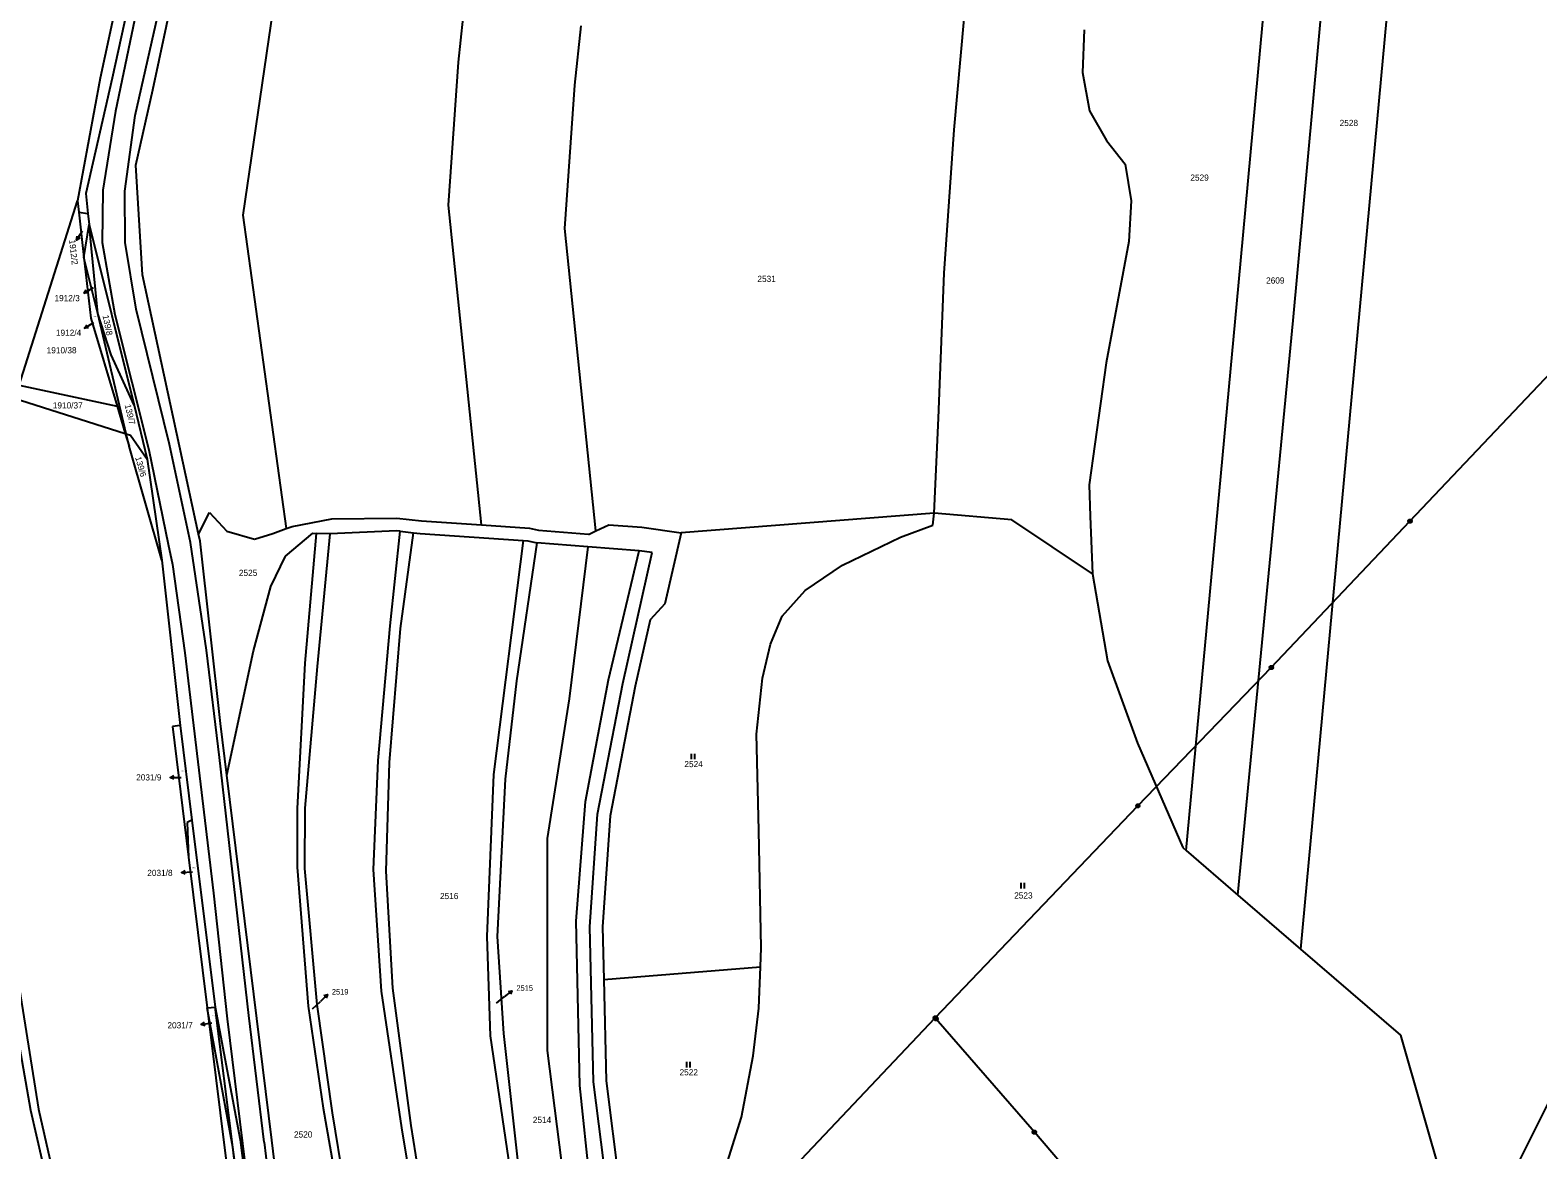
# Model space of a CAD drawing. Extents: x -609861 to -605046, y -1120287 to -1116307.
# Drawn here: x -607250.8 to -606836.4, y -1118504.6 to -1118197.1 of the extents above; entities that cross this region are included whole.
import ezdxf

# ---------------------------------------------------------------- set-up
doc = ezdxf.new("R2010")
doc.units = 0
for name, color, linetype in [('Vrstva 1', 7, 'Continuous'), ('Vrstva 2', 7, 'Continuous'), ('Vrstva 3', 7, 'Continuous'), ('Vrstva 4', 7, 'Continuous'), ('Vrstva 6', 7, 'Continuous'), ('Vrstva 7', 7, 'Continuous')]:
    doc.layers.add(name, color=color, linetype=linetype)

msp = doc.modelspace()

# ---------------------------------------------------------------- linework, layer by layer
at = {"layer": 'Vrstva 1'}
for p, q in [((-607172.46, -1118111.92), (-607192.3, -1118247.91)), ((-606918.73, -1118267.31), (-606904.4, -1118112.2)), ((-606903.66, -1118276.82), (-606888.63, -1118111.38)), ((-606870.35, -1118110.42), (-606886.02, -1118279.96)), ((-607212.94, -1118123.59), (-607231.55, -1118210.23)), ((-607209.11, -1118122.88), (-607228.2, -1118210.25)), ((-607217.05, -1118213.46), (-607198.16, -1118124.63)), ((-607133.04, -1118205.81), (-607126.84, -1118146.88)), ((-606996.8, -1118224.45), (-606994.05, -1118193.91)), ((-607101.05, -1118212.2), (-607099.33, -1118195.85)), ((-606961.13, -1118196.96), (-606961.53, -1118208.68)), ((-607135.82, -1118245.13), (-607133.04, -1118205.81)), ((-607231.55, -1118210.23), (-607237.75, -1118243.93)), ((-607228.2, -1118210.25), (-607235.42, -1118241.92)), ((-607103.83, -1118251.52), (-607101.05, -1118212.2)), ((-606961.53, -1118208.68), (-606959.68, -1118219.21)), ((-607221.72, -1118234.16), (-607217.05, -1118213.46)), ((-606959.68, -1118219.21), (-606954.98, -1118227.39)), ((-606999.58, -1118263.77), (-606996.8, -1118224.45)), ((-606954.98, -1118227.39), (-606949.83, -1118233.88)), ((-607219.92, -1118264.25), (-607221.72, -1118234.16)), ((-606949.83, -1118233.88), (-606948.16, -1118243.99)), ((-607253.78, -1118294.59), (-607237.75, -1118243.93)), ((-607237.75, -1118243.93), (-607237.39, -1118247.08)), ((-607235.42, -1118241.92), (-607234.88, -1118247.44)), ((-607126.76, -1118332.97), (-607135.82, -1118245.13)), ((-606948.16, -1118243.99), (-606948.82, -1118255.1)), ((-607237.39, -1118247.08), (-607234.88, -1118247.44)), ((-607237.39, -1118247.08), (-607235.98, -1118259.51)), ((-607234.88, -1118247.44), (-607234.58, -1118250.49)), ((-607192.3, -1118247.91), (-607180.37, -1118333.98)), ((-607235.98, -1118259.51), (-607234.58, -1118250.49)), ((-607232.18, -1118274.91), (-607234.58, -1118250.49)), ((-607234.58, -1118250.49), (-607222.16, -1118300.08)), ((-607095.27, -1118334.57), (-607103.83, -1118251.52)), ((-606948.82, -1118255.1), (-606955.03, -1118288.41)), ((-607232.18, -1118274.91), (-607235.98, -1118259.51)), ((-607235.98, -1118259.51), (-607234.08, -1118276.2)), ((-607204.46, -1118335.48), (-607219.92, -1118264.25)), ((-607001.11, -1118303.67), (-606999.58, -1118263.77)), ((-606933.06, -1118422.42), (-606918.73, -1118267.31)), ((-607234.08, -1118276.2), (-607226.84, -1118300.38)), ((-607228.45, -1118286.25), (-607232.18, -1118274.91)), ((-607224.37, -1118307.94), (-607232.18, -1118274.91)), ((-606918.9, -1118434.64), (-606903.66, -1118276.82)), ((-606886.02, -1118279.96), (-606901.68, -1118449.49)), ((-607222.16, -1118300.08), (-607228.45, -1118286.25)), ((-606955.03, -1118288.41), (-606959.74, -1118322)), ((-607253.78, -1118294.59), (-607226.84, -1118300.38)), ((-607255.46, -1118298.06), (-607224.61, -1118307.86)), ((-607226.84, -1118300.38), (-607224.61, -1118307.86)), ((-607222.16, -1118300.08), (-607218.61, -1118314.91)), ((-607002.36, -1118329.74), (-607001.11, -1118303.67)), ((-607224.61, -1118307.86), (-607223.56, -1118311.36)), ((-607224.37, -1118307.94), (-607223.19, -1118308.31)), ((-607223.56, -1118311.36), (-607224.37, -1118307.94)), ((-607214.6, -1118342.67), (-607223.56, -1118311.36)), ((-607223.19, -1118308.31), (-607218.61, -1118314.91)), ((-607218.61, -1118314.91), (-607214.6, -1118342.67)), ((-606959.74, -1118322), (-606959.43, -1118330.56)), ((-607204.46, -1118335.48), (-607201.5, -1118329.59)), ((-607201.5, -1118329.59), (-607196.7, -1118334.64)), ((-607178.71, -1118333.37), (-607167.89, -1118331.31)), ((-607167.89, -1118331.31), (-607149.98, -1118331.07)), ((-607149.98, -1118331.07), (-607143.25, -1118331.83)), ((-607143.25, -1118331.83), (-607126.76, -1118332.97)), ((-607002.36, -1118329.74), (-607071.9, -1118335.13)), ((-607002.66, -1118333.04), (-607002.36, -1118329.74)), ((-606980.96, -1118331.55), (-607002.36, -1118329.74)), ((-606958.86, -1118346.42), (-606980.96, -1118331.55)), ((-606959.43, -1118330.56), (-606958.86, -1118346.42)), ((-607204.04, -1118337.4), (-607204.46, -1118335.48)), ((-607196.7, -1118334.64), (-607189.07, -1118336.84)), ((-607189.07, -1118336.84), (-607184.05, -1118335.32)), ((-607184.05, -1118335.32), (-607180.37, -1118333.98)), ((-607180.56, -1118341.58), (-607173.06, -1118335.25)), ((-607180.37, -1118333.98), (-607178.71, -1118333.37)), ((-607172.16, -1118335.31), (-607175.25, -1118370.95)), ((-607173.06, -1118335.25), (-607172.16, -1118335.31)), ((-607168.35, -1118335.42), (-607172.16, -1118335.31)), ((-607171.79, -1118371.87), (-607168.35, -1118335.42)), ((-607150.1, -1118334.58), (-607168.35, -1118335.42)), ((-607151.84, -1118360.64), (-607149.12, -1118334.65)), ((-607149.12, -1118334.65), (-607150.1, -1118334.58)), ((-607149.12, -1118334.65), (-607145.38, -1118335.12)), ((-607149, -1118361.46), (-607145.38, -1118335.12)), ((-607145.38, -1118335.12), (-607143.57, -1118335.32)), ((-607143.57, -1118335.32), (-607115.24, -1118337.28)), ((-607126.76, -1118332.97), (-607113.57, -1118333.89)), ((-607113.57, -1118333.89), (-607111.05, -1118334.41)), ((-607111.05, -1118334.41), (-607097.3, -1118335.48)), ((-607097.3, -1118335.48), (-607097.18, -1118335.49)), ((-607097.18, -1118335.49), (-607095.27, -1118334.57)), ((-607095.27, -1118334.57), (-607091.77, -1118332.9)), ((-607091.77, -1118332.9), (-607082.69, -1118333.61)), ((-607082.69, -1118333.61), (-607071.9, -1118335.13)), ((-607071.9, -1118335.13), (-607076.3, -1118354.64)), ((-607027.54, -1118344), (-607011.59, -1118336.34)), ((-607011.59, -1118336.34), (-607002.66, -1118333.04)), ((-607198.43, -1118387.5), (-607204.04, -1118337.4)), ((-607115.24, -1118337.28), (-607123.4, -1118401.56)), ((-607111.54, -1118337.88), (-607117.09, -1118375.75)), ((-607115.24, -1118337.28), (-607114.03, -1118337.35)), ((-607114.03, -1118337.35), (-607111.54, -1118337.88)), ((-607097.47, -1118338.98), (-607111.54, -1118337.88)), ((-607097.47, -1118338.98), (-607102.63, -1118380.78)), ((-607083.4, -1118340.07), (-607097.47, -1118338.98)), ((-607091.8, -1118375.49), (-607083.4, -1118340.07)), ((-607087.92, -1118376.55), (-607079.79, -1118340.58)), ((-607079.79, -1118340.58), (-607083.4, -1118340.07)), ((-607214.6, -1118342.67), (-607209.57, -1118388.09)), ((-607184.64, -1118349.84), (-607180.56, -1118341.58)), ((-607037.75, -1118351.02), (-607027.54, -1118344)), ((-606958.86, -1118346.42), (-606954.68, -1118370.27)), ((-607189.42, -1118367.52), (-607184.64, -1118349.84)), ((-607044.13, -1118358.05), (-607037.75, -1118351.02)), ((-607076.3, -1118354.64), (-607080.38, -1118359.05)), ((-607155.09, -1118397.64), (-607151.84, -1118360.64)), ((-607152.01, -1118398.25), (-607149, -1118361.46)), ((-607080.38, -1118359.05), (-607084.49, -1118377.27)), ((-607047.32, -1118365.71), (-607044.13, -1118358.05)), ((-607196.68, -1118401.73), (-607189.42, -1118367.52)), ((-607049.55, -1118375.09), (-607047.32, -1118365.71)), ((-607175.25, -1118370.95), (-607177.42, -1118410.88)), ((-607175.14, -1118410.78), (-607171.79, -1118371.87)), ((-606954.68, -1118370.27), (-606946.43, -1118392.95)), ((-607117.09, -1118375.75), (-607120.18, -1118402.77)), ((-607098.14, -1118408.97), (-607091.8, -1118375.49)), ((-607094.87, -1118412.42), (-607087.92, -1118376.55)), ((-607084.49, -1118377.27), (-607091.39, -1118412.87)), ((-607051.14, -1118390.42), (-607049.55, -1118375.09)), ((-607102.63, -1118380.78), (-607108.64, -1118419.12)), ((-607209.57, -1118388.09), (-607211.63, -1118388.37)), ((-607211.63, -1118388.37), (-607207.21, -1118424.22)), ((-607209.57, -1118388.09), (-607206.32, -1118414.02)), ((-607196.68, -1118401.73), (-607198.43, -1118387.5)), ((-607050.5, -1118416.91), (-607051.14, -1118390.42)), ((-606946.43, -1118392.95), (-606934.03, -1118421.58)), ((-607156.38, -1118427.64), (-607155.09, -1118397.64)), ((-607152.96, -1118428.06), (-607152.01, -1118398.25)), ((-607184.37, -1118502.01), (-607196.68, -1118401.73)), ((-607123.4, -1118401.56), (-607125.22, -1118446)), ((-607120.18, -1118402.77), (-607122.42, -1118446)), ((-607177.42, -1118410.88), (-607177.42, -1118426.96)), ((-607175.23, -1118427.37), (-607175.14, -1118410.78)), ((-607100.67, -1118441.85), (-607098.14, -1118408.97)), ((-607206.32, -1118414.02), (-607207.57, -1118414.74)), ((-607207.57, -1118414.74), (-607207.21, -1118424.22)), ((-607206.32, -1118414.02), (-607199.88, -1118465.43)), ((-607096.96, -1118443.33), (-607094.87, -1118412.42)), ((-607091.39, -1118412.87), (-607093.46, -1118443.41)), ((-607108.64, -1118419.12), (-607108.64, -1118477.33)), ((-607049.86, -1118449.16), (-607050.5, -1118416.91)), ((-606934.03, -1118421.58), (-606933.06, -1118422.42)), ((-606933.06, -1118422.42), (-606918.9, -1118434.64)), ((-607207.21, -1118424.22), (-607202.11, -1118465.65)), ((-607177.42, -1118426.96), (-607174.35, -1118465.12)), ((-607171.93, -1118464.66), (-607175.23, -1118427.37)), ((-607154.21, -1118461), (-607156.38, -1118427.64)), ((-607151.1, -1118460.25), (-607152.96, -1118428.06)), ((-606918.9, -1118434.64), (-606901.68, -1118449.49)), ((-606805.82, -1118435.99), (-606851.98, -1118528.42)), ((-607099.72, -1118486.99), (-607100.67, -1118441.85)), ((-607095.91, -1118485.91), (-607096.96, -1118443.33)), ((-607093.46, -1118443.41), (-607093.1, -1118457.87)), ((-607125.22, -1118446), (-607124.32, -1118473.3)), ((-607122.42, -1118446), (-607120.64, -1118472.66)), ((-607050.06, -1118454.33), (-607049.86, -1118449.16)), ((-606901.68, -1118449.49), (-606874.22, -1118473.16)), ((-607254.29, -1118456.53), (-607248.49, -1118493.49)), ((-607093.1, -1118457.87), (-607050.06, -1118454.33)), ((-607050.5, -1118465.67), (-607050.06, -1118454.33)), ((-607257.06, -1118456.98), (-607250.62, -1118493.73)), ((-607146.07, -1118497.94), (-607151.1, -1118460.25)), ((-607093.1, -1118457.87), (-607092.42, -1118485.65)), ((-607167.71, -1118494.46), (-607171.93, -1118464.66)), ((-607148.58, -1118498.62), (-607154.21, -1118461)), ((-607202.11, -1118465.65), (-607199.88, -1118465.43)), ((-607195.06, -1118503.92), (-607202.11, -1118465.65)), ((-607202.11, -1118465.65), (-607197.37, -1118504.09)), ((-607195.06, -1118503.92), (-607199.88, -1118465.43)), ((-607199.88, -1118465.43), (-607193.08, -1118501.84)), ((-607174.35, -1118465.12), (-607170.21, -1118493.2)), ((-607052.09, -1118478.76), (-607050.5, -1118465.67)), ((-607124.32, -1118473.3), (-607118.94, -1118509.95)), ((-607120.64, -1118472.66), (-607116.66, -1118509.04)), ((-606874.22, -1118473.16), (-606857.36, -1118531.64)), ((-607108.64, -1118477.33), (-607103.27, -1118519.64)), ((-607055.28, -1118495.68), (-607052.09, -1118478.76)), ((-607092.42, -1118485.65), (-607088.74, -1118515.16)), ((-607095.7, -1118525.1), (-607099.72, -1118486.99)), ((-607091.13, -1118524.28), (-607095.91, -1118485.91)), ((-607250.62, -1118493.73), (-607238.38, -1118547.37)), ((-607248.49, -1118493.49), (-607236.26, -1118546.93)), ((-607170.21, -1118493.2), (-607162.96, -1118534.58)), ((-607161.12, -1118534.04), (-607167.71, -1118494.46)), ((-607139.78, -1118536.75), (-607146.07, -1118497.94)), ((-607062.62, -1118518.98), (-607055.28, -1118495.68)), ((-607193.08, -1118501.84), (-607179.6, -1118606.23)), ((-607171.11, -1118605.54), (-607184.37, -1118502.01)), ((-607142.16, -1118537.19), (-607148.58, -1118498.62)), ((-607197.37, -1118504.09), (-607189.06, -1118569.6)), ((-607182.6, -1118596.66), (-607195.06, -1118503.92)), ((-607187.79, -1118564.73), (-607195.06, -1118503.92))]:
    msp.add_line(p, q, dxfattribs=at)
at = {"layer": 'Vrstva 3'}
for p, q in [((-607069.11, -1118395.8), (-607069.11, -1118397.3)), ((-607068.11, -1118397.3), (-607068.11, -1118395.8)), ((-606978.48, -1118431.3), (-606978.48, -1118432.8)), ((-606977.48, -1118432.8), (-606977.48, -1118431.3)), ((-607070.37, -1118480.47), (-607070.37, -1118481.97)), ((-607069.37, -1118481.97), (-607069.37, -1118480.47))]:
    msp.add_line(p, q, dxfattribs=at)
at = {"layer": 'Vrstva 4'}
for p, q in [((-607219.45, -1118181.73), (-607227.28, -1118219.31)), ((-607221.87, -1118220.52), (-607213.45, -1118182.9)), ((-607227.28, -1118219.31), (-607230.78, -1118241.02)), ((-607224.78, -1118241.29), (-607221.87, -1118220.52)), ((-607230.78, -1118241.02), (-607230.98, -1118255.4)), ((-607224.68, -1118255.38), (-607224.78, -1118241.29)), ((-607230.98, -1118255.4), (-607227.5, -1118275.18)), ((-607221.66, -1118273.69), (-607224.68, -1118255.38)), ((-607212.45, -1118310.87), (-607221.66, -1118273.69)), ((-607227.5, -1118275.18), (-607218.14, -1118312.3)), ((-607206.72, -1118337.75), (-607212.45, -1118310.87)), ((-607218.14, -1118312.3), (-607212.82, -1118338.27)), ((-607212.82, -1118338.27), (-607211.6, -1118343.82)), ((-607202.28, -1118367.34), (-607206.72, -1118337.75)), ((-607211.6, -1118343.82), (-607208.22, -1118368.1)), ((-607208.22, -1118368.1), (-607200.4, -1118434.15)), ((-607198.72, -1118396.82), (-607202.28, -1118367.34)), ((-607190.64, -1118467.75), (-607198.72, -1118396.82)), ((-607200.4, -1118434.15), (-607196.66, -1118468.6)), ((-607196.66, -1118468.6), (-607188.25, -1118535.94)), ((-607186.47, -1118502.52), (-607190.64, -1118467.75)), ((-607186.47, -1118502.52), (-607174.59, -1118597.34))]:
    msp.add_line(p, q, dxfattribs=at)
at = {"layer": 'Vrstva 6'}
for p, q in [((-606871.61, -1118331.95), (-606829.45, -1118287.55)), ((-606909.71, -1118372.14), (-606871.61, -1118331.95)), ((-606946.37, -1118410.11), (-606909.71, -1118372.14)), ((-607002.05, -1118468.39), (-606946.37, -1118410.11)), ((-607046.72, -1118515.53), (-607002.05, -1118468.39)), ((-606974.78, -1118499.79), (-607001.86, -1118468.65)), ((-606930.18, -1118551.66), (-606974.78, -1118499.79))]:
    msp.add_line(p, q, dxfattribs=at)
for points in [[(-606871.76, -1118331.47), (-606871.45, -1118331.47), (-606871.2, -1118331.65), (-606871.1, -1118331.94), (-606871.2, -1118332.23), (-606871.45, -1118332.41), (-606871.76, -1118332.41), (-606872.01, -1118332.23), (-606872.11, -1118331.94), (-606872.01, -1118331.65), (-606871.76, -1118331.47), (-606871.73, -1118331.51), (-606871.49, -1118331.51), (-606871.33, -1118331.59), (-606871.89, -1118331.59), (-606871.97, -1118331.67), (-606871.25, -1118331.67), (-606871.25, -1118331.75), (-606871.97, -1118331.75), (-606872.01, -1118331.83), (-606871.21, -1118331.83), (-606871.17, -1118331.91), (-606872.05, -1118331.91), (-606872.05, -1118331.99), (-606871.17, -1118331.99), (-606871.2, -1118332.07), (-606872.01, -1118332.07), (-606872, -1118332.15), (-606871.19, -1118332.15), (-606871.24, -1118332.23), (-606871.96, -1118332.23), (-606871.88, -1118332.31), (-606871.32, -1118332.31), (-606871.43, -1118332.39), (-606871.77, -1118332.39)], [(-606909.86, -1118371.66), (-606909.55, -1118371.66), (-606909.3, -1118371.84), (-606909.2, -1118372.13), (-606909.3, -1118372.42), (-606909.55, -1118372.6), (-606909.86, -1118372.6), (-606910.11, -1118372.42), (-606910.21, -1118372.13), (-606910.11, -1118371.84), (-606909.86, -1118371.66), (-606909.83, -1118371.7), (-606909.59, -1118371.7), (-606909.43, -1118371.78), (-606909.99, -1118371.78), (-606910.07, -1118371.86), (-606909.35, -1118371.86), (-606909.35, -1118371.94), (-606910.07, -1118371.94), (-606910.11, -1118372.02), (-606909.31, -1118372.02), (-606909.27, -1118372.1), (-606910.15, -1118372.1), (-606910.15, -1118372.18), (-606909.27, -1118372.18), (-606909.3, -1118372.26), (-606910.11, -1118372.26), (-606910.1, -1118372.34), (-606909.29, -1118372.34), (-606909.34, -1118372.42), (-606910.06, -1118372.42), (-606909.98, -1118372.5), (-606909.42, -1118372.5), (-606909.53, -1118372.58), (-606909.87, -1118372.58)], [(-606946.52, -1118409.63), (-606946.21, -1118409.63), (-606945.96, -1118409.81), (-606945.86, -1118410.1), (-606945.96, -1118410.39), (-606946.21, -1118410.57), (-606946.52, -1118410.57), (-606946.77, -1118410.39), (-606946.87, -1118410.1), (-606946.77, -1118409.81), (-606946.52, -1118409.63), (-606946.49, -1118409.67), (-606946.25, -1118409.67), (-606946.09, -1118409.75), (-606946.65, -1118409.75), (-606946.73, -1118409.83), (-606946.01, -1118409.83), (-606946.01, -1118409.91), (-606946.73, -1118409.91), (-606946.77, -1118409.99), (-606945.97, -1118409.99), (-606945.93, -1118410.07), (-606946.81, -1118410.07), (-606946.81, -1118410.15), (-606945.93, -1118410.15), (-606945.96, -1118410.23), (-606946.77, -1118410.23), (-606946.76, -1118410.31), (-606945.95, -1118410.31), (-606946, -1118410.39), (-606946.72, -1118410.39), (-606946.64, -1118410.47), (-606946.08, -1118410.47), (-606946.19, -1118410.55), (-606946.53, -1118410.55)], [(-607002.2, -1118467.91), (-607001.89, -1118467.91), (-607001.64, -1118468.09), (-607001.54, -1118468.38), (-607001.64, -1118468.67), (-607001.89, -1118468.85), (-607002.2, -1118468.85), (-607002.45, -1118468.67), (-607002.55, -1118468.38), (-607002.45, -1118468.09), (-607002.2, -1118467.91), (-607002.17, -1118467.95), (-607001.93, -1118467.95), (-607001.77, -1118468.03), (-607002.33, -1118468.03), (-607002.41, -1118468.11), (-607001.69, -1118468.11), (-607001.69, -1118468.19), (-607002.41, -1118468.19), (-607002.45, -1118468.27), (-607001.65, -1118468.27), (-607001.61, -1118468.35), (-607002.49, -1118468.35), (-607002.49, -1118468.43), (-607001.61, -1118468.43), (-607001.64, -1118468.51), (-607002.45, -1118468.51), (-607002.44, -1118468.59), (-607001.63, -1118468.59), (-607001.68, -1118468.67), (-607002.4, -1118468.67), (-607002.32, -1118468.75), (-607001.76, -1118468.75), (-607001.87, -1118468.83), (-607002.21, -1118468.83)], [(-607002.01, -1118468.17), (-607001.7, -1118468.17), (-607001.45, -1118468.35), (-607001.35, -1118468.64), (-607001.45, -1118468.93), (-607001.7, -1118469.11), (-607002.01, -1118469.11), (-607002.26, -1118468.93), (-607002.36, -1118468.64), (-607002.26, -1118468.35), (-607002.01, -1118468.17), (-607001.98, -1118468.21), (-607001.74, -1118468.21), (-607001.58, -1118468.29), (-607002.14, -1118468.29), (-607002.22, -1118468.37), (-607001.5, -1118468.37), (-607001.5, -1118468.45), (-607002.22, -1118468.45), (-607002.26, -1118468.53), (-607001.46, -1118468.53), (-607001.42, -1118468.61), (-607002.3, -1118468.61), (-607002.3, -1118468.69), (-607001.42, -1118468.69), (-607001.45, -1118468.77), (-607002.26, -1118468.77), (-607002.25, -1118468.85), (-607001.44, -1118468.85), (-607001.49, -1118468.93), (-607002.21, -1118468.93), (-607002.13, -1118469.01), (-607001.57, -1118469.01), (-607001.68, -1118469.09), (-607002.02, -1118469.09)], [(-606974.93, -1118499.31), (-606974.62, -1118499.31), (-606974.37, -1118499.49), (-606974.27, -1118499.78), (-606974.37, -1118500.07), (-606974.62, -1118500.25), (-606974.93, -1118500.25), (-606975.18, -1118500.07), (-606975.28, -1118499.78), (-606975.18, -1118499.49), (-606974.93, -1118499.31), (-606974.9, -1118499.35), (-606974.66, -1118499.35), (-606974.5, -1118499.43), (-606975.06, -1118499.43), (-606975.14, -1118499.51), (-606974.42, -1118499.51), (-606974.42, -1118499.59), (-606975.14, -1118499.59), (-606975.18, -1118499.67), (-606974.38, -1118499.67), (-606974.34, -1118499.75), (-606975.22, -1118499.75), (-606975.22, -1118499.83), (-606974.34, -1118499.83), (-606974.37, -1118499.91), (-606975.18, -1118499.91), (-606975.17, -1118499.99), (-606974.36, -1118499.99), (-606974.41, -1118500.07), (-606975.13, -1118500.07), (-606975.05, -1118500.15), (-606974.49, -1118500.15), (-606974.6, -1118500.23), (-606974.94, -1118500.23)]]:
    msp.add_lwpolyline(points, dxfattribs=at)
at = {"layer": 'Vrstva 7'}
for p, q in [((-607238.003, -1118254.733), (-607236.35, -1118252.23)), ((-607235.921, -1118269.326), (-607233.35, -1118267.78)), ((-607235.817, -1118278.943), (-607233.25, -1118277.39)), ((-607212.25, -1118402.311), (-607209.25, -1118402.31)), ((-607209.161, -1118428.471), (-607206.17, -1118428.24)), ((-607173.15, -1118465.91), (-607171, -1118463.84)), ((-607169.057, -1118461.965), (-607171, -1118463.84)), ((-607122.58, -1118464.31), (-607120.46, -1118462.62)), ((-607118.345, -1118460.942), (-607120.46, -1118462.62)), ((-607203.757, -1118470.238), (-607200.8, -1118469.73))]:
    msp.add_line(p, q, dxfattribs=at)
for points in [[(-607237.035, -1118254.174), (-607238.003, -1118254.733), (-607237.869, -1118253.623)], [(-607234.807, -1118269.239), (-607235.921, -1118269.326), (-607235.322, -1118268.382)], [(-607234.702, -1118278.853), (-607235.817, -1118278.943), (-607235.22, -1118277.998)], [(-607211.25, -1118402.81), (-607212.25, -1118402.311), (-607211.25, -1118401.81)], [(-607208.125, -1118428.893), (-607209.161, -1118428.471), (-607208.203, -1118427.896)], [(-607170.017, -1118462.266), (-607169.057, -1118461.965), (-607169.392, -1118462.914)], [(-607119.329, -1118461.149), (-607118.345, -1118460.942), (-607118.77, -1118461.854)], [(-607202.686, -1118470.562), (-607203.757, -1118470.238), (-607202.856, -1118469.576)]]:
    msp.add_lwpolyline(points, dxfattribs=at)

# ---------------------------------------------------------------- texts
at = {"layer": 'Vrstva 2'}
for s, height, p in [('2528', 1.7, (-606890.903, -1118223.4)), ('2529', 1.7, (-606931.923, -1118238.42)), ('1912/2', 0.2, (-607235.864, -1118250.5)), ('1912/3', 0.2, (-607234.604, -1118260.6)), ('2531', 1.7, (-607050.903, -1118266.23)), ('2609', 1.7, (-606911.113, -1118266.67)), ('1912/4', 0.2, (-607233.304, -1118275.81)), ('1910/38', 1.7, (-607246.217, -1118285.84)), ('1910/37', 1.7, (-607244.537, -1118300.98)), ('2525', 1.7, (-607193.393, -1118346.98)), ('2524', 1.7, (-607070.973, -1118399.5)), ('2031/9', 0.2, (-607209.222, -1118400.7)), ('2031/8', 0.2, (-607206.142, -1118427.26)), ('2516', 1.7, (-607138.133, -1118435.75)), ('2523', 1.7, (-606980.333, -1118435.59)), ('2515', 0.1, (-607122.566, -1118464.31)), ('2031/7', 0.2, (-607200.772, -1118467.98)), ('2519', 0.1, (-607173.136, -1118465.91)), ('2522', 1.7, (-607072.303, -1118484.17)), ('2514', 1.7, (-607112.623, -1118497.23)), ('2520', 1.7, (-607178.253, -1118501.24))]:
    msp.add_text(s, height=height, dxfattribs=at).set_placement(p)
for s, rotation, p in [('139/8', 281.72335, (-607230.87, -1118275.495)), ('139/7', 283.49952, (-607224.788, -1118300.052)), ('139/6', 285.27569, (-607221.917, -1118314.429))]:
    msp.add_text(s, height=1.7, rotation=rotation, dxfattribs=at).set_placement(p)
at = {"layer": 'Vrstva 7'}
msp.add_text('1912/2', height=1.7, rotation=276.28025, dxfattribs=at).set_placement((-607240.048, -1118254.685))
for s, height, p in [('1912/3', 1.7, (-607244.072, -1118271.51)), ('1912/4', 1.7, (-607243.678, -1118281.02)), ('2031/9', 1.7, (-607221.622, -1118403.16)), ('2031/8', 1.7, (-607218.572, -1118429.4)), ('2519', 1.53, (-607167.846, -1118461.97)), ('2515', 1.53, (-607117.126, -1118460.94)), ('2031/7', 1.7, (-607213.031, -1118471.25))]:
    msp.add_text(s, height=height, dxfattribs=at).set_placement(p)

doc.saveas('drawing.dxf')
